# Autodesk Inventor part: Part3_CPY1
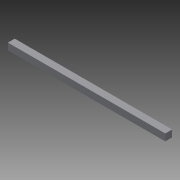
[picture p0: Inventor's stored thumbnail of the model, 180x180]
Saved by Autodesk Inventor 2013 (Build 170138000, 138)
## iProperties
Created: 2013-06
Part Number: Part3_CPY1
Material: Generic
Document SubType Name: Modeling
Designer: jpfenske
Mass: 1272.05 g
Surface Area: 1364.51 cm^2
Volume: 1272.05 cm^3
Density: 1 g/cm^3
Author: jpfenske
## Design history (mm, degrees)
sketch "Sketch1"
  geometry: L1 (-414.892, 325.462)-(461.408, 325.462); L2 (461.408, 325.462)-(461.408, 287.362); L3 (461.408, 287.362)-(-414.892, 287.362); L4 (-414.892, 287.362)-(-414.892, 325.462); 1 further point
  constraints: 8 end point, 2 parallel, 1 horizontal, 1 perpendicular
  dimensions: "d0" = 876.3 distance of L1.start L1.end; "d1" = 38.1 distance of L1.end L2.end
extrude "Extrusion1" new body sketch "Sketch1" distance "d2" = 38.1; taper "d3" = 0 deg
body "Solid1"
